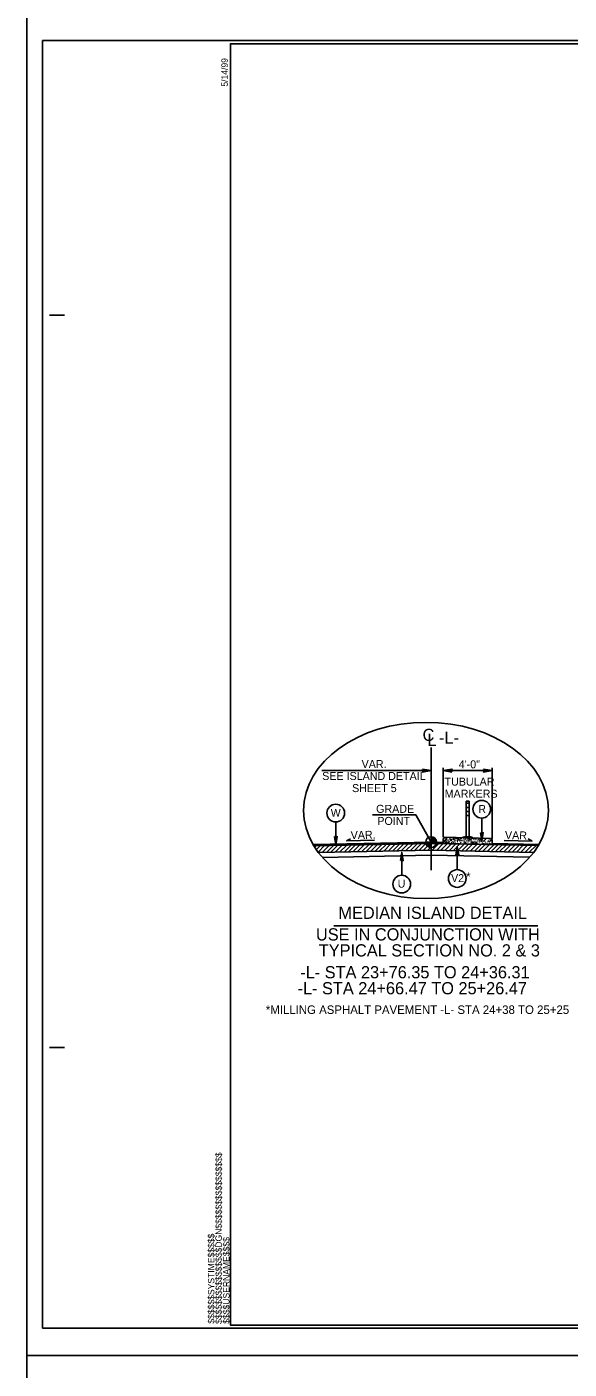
# Model space of a CAD drawing. Extents: x 1901718 to 1902220, y 193828 to 194187.
# Drawn here: x 1901965.8 to 1902010.3, y 193936.9 to 194046.9 of the extents above; entities that cross this region are included whole.
import ezdxf

# ---------------------------------------------------------------- set-up
doc = ezdxf.new("R2010")
doc.units = 0
for name, color, linetype in [('Old_Level_1', 7, 'Continuous'), ('Old_Level_11', 7, 'Continuous'), ('Old_Level_19', 7, 'Continuous'), ('Old_Level_2', 7, 'Continuous'), ('Old_Level_20', 7, 'Continuous'), ('Old_Level_3', 7, 'Continuous'), ('Prop Dimension', 7, 'Continuous'), ('Prop Dimension Text', 7, 'Continuous'), ('Sheet Border Standard 30in CELL', 7, 'Continuous'), ('Sheet Cutting Line CELL', 7, 'Continuous'), ('Sheet Plot Border Inside CELL', 7, 'Continuous'), ('Sheet Plot Border Outside CELL', 7, 'Continuous'), ('Typical Curb CELL', 7, 'Continuous'), ('Typical Terminator CELL', 7, 'Continuous')]:
    doc.layers.add(name, color=color, linetype=linetype)

# ---------------------------------------------------------------- blocks, each defined once
blk = doc.blocks.new('TERMINATOR')
at = {"layer": 'Typical Terminator CELL'}
blk.add_lwpolyline([(-0.469, 0.081), (0, 0), (-0.471, -0.083), (-0.411, 0)], close=True, dxfattribs=at)

msp = doc.modelspace()

# ---------------------------------------------------------------- linework, layer by layer
at = {"layer": 'Old_Level_1'}
for p, q in [((1901998.99, 193977.77), (1901998.99, 193987.83)), ((1901999.99, 193980.5), (1901999.99, 193986.17)), ((1902001.87, 193980.52), (1902001.87, 193983.43)), ((1902001.87, 193983.43), (1902002.12, 193983.43)), ((1902001.87, 193983.26), (1902002.12, 193983.26)), ((1902001.87, 193982.93), (1902002.12, 193982.93)), ((1902002.12, 193980.51), (1902002.12, 193983.43)), ((1902001.87, 193982.59), (1902002.12, 193982.59)), ((1902001.87, 193982.26), (1902002.12, 193982.26)), ((1901998.99, 193980.08), (1901989.32, 193979.89)), ((1901998.99, 193979.98), (1901989.38, 193979.78)), ((1901989.44, 193979.69), (1901989.54, 193979.79)), ((1901989.58, 193979.47), (1901989.9, 193979.79)), ((1901989.73, 193979.27), (1901990.26, 193979.8)), ((1901990.05, 193979.23), (1901990.62, 193979.81)), ((1901990.41, 193979.24), (1901990.98, 193979.81)), ((1901990.77, 193979.25), (1901991.34, 193979.82)), ((1901991.13, 193979.26), (1901991.7, 193979.83)), ((1901991.49, 193979.26), (1901992.07, 193979.84)), ((1901991.85, 193979.27), (1901992.43, 193979.84)), ((1901992.05, 193980.2), (1901992.38, 193980.36)), ((1901994.35, 193980.24), (1901992.05, 193980.2)), ((1901992.21, 193979.28), (1901992.79, 193979.85)), ((1901992.57, 193979.28), (1901993.15, 193979.86)), ((1901992.93, 193979.29), (1901993.51, 193979.87)), ((1901993.3, 193979.3), (1901993.87, 193979.87)), ((1901993.66, 193979.31), (1901994.23, 193979.88)), ((1901994.02, 193979.31), (1901994.59, 193979.89)), ((1901994.38, 193979.32), (1901994.95, 193979.89)), ((1901994.74, 193979.33), (1901995.31, 193979.9)), ((1901995.1, 193979.34), (1901995.67, 193979.91)), ((1901995.46, 193979.34), (1901996.03, 193979.92)), ((1901995.82, 193979.35), (1901996.39, 193979.92)), ((1901995.82, 193979.35), (1901996.01, 193979.54)), ((1901996.18, 193979.36), (1901996.76, 193979.93)), ((1901996.54, 193979.36), (1901997.12, 193979.94)), ((1901996.9, 193979.37), (1901997.48, 193979.94)), ((1901997.26, 193979.38), (1901997.84, 193979.95)), ((1901997.62, 193979.39), (1901998.2, 193979.96)), ((1901997.99, 193979.39), (1901998.56, 193979.97)), ((1901998.35, 193979.4), (1901998.7, 193979.75)), ((1901998.55, 193980.08), (1901998.99, 193980.08)), ((1901998.71, 193979.41), (1901998.94, 193979.64)), ((1901998.99, 193980.08), (1901998.99, 193980.52)), ((1901998.99, 193980.08), (1901999.99, 193980.06)), ((1901999.43, 193980.08), (1901998.99, 193980.08)), ((1901998.99, 193979.64), (1901998.99, 193980.08)), ((1901998.99, 193980.08), (1901998.99, 193979.64)), ((1901998.99, 193979.98), (1902007.77, 193979.8)), ((1901999.07, 193979.41), (1901999.62, 193979.96)), ((1901999.42, 193979.4), (1901999.97, 193979.96)), ((1901999.76, 193979.4), (1902000.31, 193979.95)), ((1902000.11, 193979.39), (1902000.66, 193979.94)), ((1902000.46, 193979.38), (1902001.01, 193979.93)), ((1902000.8, 193979.38), (1902001.35, 193979.93)), ((1902001.15, 193979.37), (1902001.7, 193979.92)), ((1902001.5, 193979.36), (1902002.05, 193979.91)), ((1902001.84, 193979.36), (1902002.39, 193979.91)), ((1902002.19, 193979.35), (1902002.74, 193979.9)), ((1902002.54, 193979.34), (1902003.09, 193979.89)), ((1902002.88, 193979.34), (1902003.43, 193979.89)), ((1902003.23, 193979.33), (1902003.78, 193979.88)), ((1902003.58, 193979.32), (1902004.13, 193979.87)), ((1902003.92, 193979.31), (1902004.47, 193979.87)), ((1902003.99, 193979.98), (1902007.84, 193979.9)), ((1902004.27, 193979.31), (1902004.82, 193979.86)), ((1902004.61, 193979.3), (1902005.17, 193979.85)), ((1902004.96, 193979.29), (1902005.51, 193979.84)), ((1902004.97, 193980.22), (1902007.27, 193980.17)), ((1902005.31, 193979.29), (1902005.86, 193979.84)), ((1902005.65, 193979.28), (1902006.21, 193979.83)), ((1902006, 193979.27), (1902006.55, 193979.82)), ((1902006.35, 193979.27), (1902006.9, 193979.82)), ((1902006.69, 193979.26), (1902007.25, 193979.81)), ((1902007.27, 193980.17), (1902006.95, 193980.36)), ((1902007.04, 193979.25), (1902007.59, 193979.8)), ((1901998.99, 193979.41), (1901989.76, 193979.23)), ((1901998.99, 193979), (1901990.09, 193978.82)), ((1901998.99, 193979.41), (1902007.4, 193979.24)), ((1901998.99, 193979), (1902007.07, 193978.84)), ((1902000.8, 193979.38), (1902000.85, 193979.42)), ((1902007.39, 193979.25), (1902007.45, 193979.3))]:
    msp.add_line(p, q, dxfattribs=at)
for points in [[(1902001.87, 193983.26), (1902002.12, 193983.26), (1902002.12, 193982.93), (1902001.87, 193982.93)], [(1902001.87, 193982.59), (1902002.12, 193982.59), (1902002.12, 193982.26), (1902001.87, 193982.26)]]:
    msp.add_lwpolyline(points, close=True, dxfattribs=at)
for points in [[(1901998.55, 193980.08), (1901998.55, 193980.03)], [(1901998.56, 193980.08), (1901998.56, 193979.98)], [(1901998.57, 193980.08), (1901998.57, 193979.95)], [(1901998.58, 193980.08), (1901998.58, 193979.92)], [(1901998.59, 193980.08), (1901998.59, 193979.9)], [(1901998.6, 193980.08), (1901998.6, 193979.88)], [(1901998.6, 193980.08), (1901998.6, 193979.87)], [(1901998.61, 193980.08), (1901998.61, 193979.85)], [(1901998.62, 193980.08), (1901998.62, 193979.84)], [(1901998.63, 193980.08), (1901998.63, 193979.82)], [(1901998.64, 193980.08), (1901998.64, 193979.81)], [(1901998.65, 193980.08), (1901998.65, 193979.8)], [(1901998.66, 193980.08), (1901998.66, 193979.79)], [(1901998.67, 193980.08), (1901998.67, 193979.78)], [(1901998.68, 193980.08), (1901998.68, 193979.77)], [(1901998.68, 193980.08), (1901998.68, 193979.76)], [(1901998.69, 193980.08), (1901998.69, 193979.75)], [(1901998.7, 193980.08), (1901998.7, 193979.75)], [(1901998.71, 193980.08), (1901998.71, 193979.74)], [(1901998.72, 193980.08), (1901998.72, 193979.73)], [(1901998.73, 193980.08), (1901998.73, 193979.72)], [(1901998.74, 193980.08), (1901998.74, 193979.72)], [(1901998.75, 193980.08), (1901998.75, 193979.71)], [(1901998.75, 193980.08), (1901998.75, 193979.71)], [(1901998.76, 193980.08), (1901998.76, 193979.7)], [(1901998.77, 193980.08), (1901998.77, 193979.7)], [(1901998.78, 193980.08), (1901998.78, 193979.69)], [(1901998.79, 193980.08), (1901998.79, 193979.69)], [(1901998.8, 193980.08), (1901998.8, 193979.68)], [(1901998.81, 193980.08), (1901998.81, 193979.68)], [(1901998.82, 193980.08), (1901998.82, 193979.67)], [(1901998.82, 193980.08), (1901998.82, 193979.67)], [(1901998.83, 193980.08), (1901998.83, 193979.67)], [(1901998.84, 193980.08), (1901998.84, 193979.66)], [(1901998.85, 193980.08), (1901998.85, 193979.66)], [(1901998.86, 193980.08), (1901998.86, 193979.66)], [(1901998.87, 193980.08), (1901998.87, 193979.66)], [(1901998.88, 193980.08), (1901998.88, 193979.65)], [(1901998.89, 193980.08), (1901998.89, 193979.65)], [(1901998.9, 193980.08), (1901998.9, 193979.65)], [(1901998.9, 193980.08), (1901998.9, 193979.65)], [(1901998.91, 193980.08), (1901998.91, 193979.64)], [(1901998.92, 193980.08), (1901998.92, 193979.64)], [(1901998.93, 193980.08), (1901998.93, 193979.64)], [(1901998.94, 193980.08), (1901998.94, 193979.64)], [(1901998.95, 193980.08), (1901998.95, 193979.64)], [(1901998.96, 193980.08), (1901998.96, 193979.64)], [(1901998.97, 193980.08), (1901998.97, 193979.64)], [(1901998.97, 193980.08), (1901998.97, 193979.64)], [(1901998.98, 193980.08), (1901998.98, 193979.64), (1901998.98, 193979.64)], [(1901998.99, 193980.52), (1901998.99, 193980.52), (1901998.99, 193980.08)], [(1901999, 193980.52), (1901999, 193980.08)], [(1901999.01, 193980.52), (1901999.01, 193980.08)], [(1901999.02, 193980.52), (1901999.02, 193980.08)], [(1901999.03, 193980.52), (1901999.03, 193980.08)], [(1901999.04, 193980.52), (1901999.04, 193980.08)], [(1901999.05, 193980.52), (1901999.05, 193980.08)], [(1901999.06, 193980.52), (1901999.06, 193980.08)], [(1901999.07, 193980.51), (1901999.07, 193980.08)], [(1901999.07, 193980.51), (1901999.07, 193980.08)], [(1901999.08, 193980.51), (1901999.08, 193980.08)], [(1901999.09, 193980.51), (1901999.09, 193980.08)], [(1901999.1, 193980.51), (1901999.1, 193980.08)], [(1901999.11, 193980.5), (1901999.11, 193980.08)], [(1901999.12, 193980.5), (1901999.12, 193980.08)], [(1901999.13, 193980.5), (1901999.13, 193980.08)], [(1901999.14, 193980.5), (1901999.14, 193980.08)], [(1901999.14, 193980.49), (1901999.14, 193980.08)], [(1901999.15, 193980.49), (1901999.15, 193980.08)], [(1901999.16, 193980.48), (1901999.16, 193980.08)], [(1901999.17, 193980.48), (1901999.17, 193980.08)], [(1901999.18, 193980.48), (1901999.18, 193980.08)], [(1901999.19, 193980.47), (1901999.19, 193980.08)], [(1901999.2, 193980.47), (1901999.2, 193980.08)], [(1901999.21, 193980.46), (1901999.21, 193980.08)], [(1901999.22, 193980.46), (1901999.22, 193980.08)], [(1901999.22, 193980.45), (1901999.22, 193980.08)], [(1901999.23, 193980.45), (1901999.23, 193980.08)], [(1901999.24, 193980.44), (1901999.24, 193980.08)], [(1901999.25, 193980.43), (1901999.25, 193980.08)], [(1901999.26, 193980.43), (1901999.26, 193980.08)], [(1901999.27, 193980.42), (1901999.27, 193980.08)], [(1901999.28, 193980.41), (1901999.28, 193980.08)], [(1901999.29, 193980.41), (1901999.29, 193980.08)], [(1901999.29, 193980.4), (1901999.29, 193980.08)], [(1901999.3, 193980.39), (1901999.3, 193980.08)], [(1901999.31, 193980.38), (1901999.31, 193980.08)], [(1901999.32, 193980.37), (1901999.32, 193980.08)], [(1901999.33, 193980.36), (1901999.33, 193980.08)], [(1901999.34, 193980.35), (1901999.34, 193980.08)], [(1901999.35, 193980.34), (1901999.35, 193980.08)], [(1901999.36, 193980.33), (1901999.36, 193980.08)], [(1901999.36, 193980.31), (1901999.36, 193980.08)], [(1901999.37, 193980.3), (1901999.37, 193980.08)], [(1901999.38, 193980.28), (1901999.38, 193980.08)], [(1901999.39, 193980.26), (1901999.39, 193980.08)], [(1901999.4, 193980.24), (1901999.4, 193980.08)], [(1901999.41, 193980.22), (1901999.41, 193980.08)], [(1901999.42, 193980.19), (1901999.42, 193980.08)], [(1901999.43, 193980.14), (1901999.43, 193980.08)]]:
    msp.add_lwpolyline(points, dxfattribs=at)
msp.add_circle((1901998.99, 193980.08), 0.441, dxfattribs=at)
for start, end in [(179.9905, 269.9905), (359.9905, 89.9905)]:
    msp.add_arc((1901998.99, 193980.08), 0.441, start, end, dxfattribs=at)
msp.add_ellipse((1902001.99, 193980.43), major_axis=(0.448, -0.012), ratio=0.205578, start_param=6.283185, end_param=9.424778, dxfattribs=at)
at = {"layer": 'Old_Level_11'}
for p, q in [((1901991.17, 193981.74), (1901991.17, 193979.86)), ((1902003.14, 193982.05), (1902003.14, 193980.18)), ((1902001.13, 193977.83), (1902001.13, 193979.7)), ((1901996.58, 193977.36), (1901996.58, 193979.24)), ((1901991.02, 193973.22), (1902007.74, 193973.22))]:
    msp.add_line(p, q, dxfattribs=at)
for points in [[(1902003.03, 193980.85), (1902003.14, 193980.18), (1902003.26, 193980.85), (1902003.14, 193980.77)], [(1901991.06, 193980.53), (1901991.17, 193979.86), (1901991.29, 193980.54), (1901991.17, 193980.45)], [(1902001.01, 193979.03), (1902001.13, 193979.7), (1902001.25, 193979.03), (1902001.13, 193979.11)], [(1901996.47, 193978.57), (1901996.58, 193979.24), (1901996.7, 193978.56), (1901996.58, 193978.65)]]:
    msp.add_lwpolyline(points, close=True, dxfattribs=at)
for centre in [(1901991.17, 193982.46), (1902003.14, 193982.78), (1901996.58, 193976.64), (1902001.13, 193977.1)]:
    msp.add_circle(centre, 0.725, dxfattribs=at)
at = {"layer": 'Old_Level_3'}
for q in [(1901994.19, 193982.32), (1901998.99, 193980.08)]:
    msp.add_line((1901997.75, 193982.32), q, dxfattribs=at)
at = {"layer": 'Prop Dimension'}
for p, q in [((1902003.99, 193980.37), (1902003.99, 193986.17)), ((1901990.02, 193985.94), (1901998.99, 193985.94)), ((1901999.99, 193985.94), (1902003.99, 193985.94))]:
    msp.add_line(p, q, dxfattribs=at)
at = {"layer": 'Sheet Border Standard 30in CELL'}
for p, q in [((1901982.64, 194045.51), (1901982.64, 194045.51)), ((1901967.69, 194023.26), (1901968.94, 194023.26)), ((1901967.69, 193963.26), (1901968.94, 193963.26))]:
    msp.add_line(p, q, dxfattribs=at)
msp.add_lwpolyline([(1902132.54, 194045.51), (1901982.54, 194045.51), (1901982.54, 193940.51), (1902132.54, 193940.51)], close=True, dxfattribs=at)
at = {"layer": 'Sheet Cutting Line CELL'}
for p, q in [((1901965.84, 194048.01), (1901965.84, 193938.01)), ((1901965.84, 193938.01), (1902134.24, 193938.01)), ((1902134.24, 193938.01), (1901965.84, 193938.01)), ((1901965.84, 193938.01), (1901965.84, 193828.01))]:
    msp.add_line(p, q, dxfattribs=at)
at = {"layer": 'Sheet Plot Border Inside CELL'}
msp.add_lwpolyline([(1902133.79, 194045.77), (1901967.14, 194045.77), (1901967.14, 193940.26), (1902133.79, 193940.26)], close=True, dxfattribs=at)
at = {"layer": 'Sheet Plot Border Outside CELL'}
for points in [[(1902134.24, 194048.01), (1901965.84, 194048.01), (1901965.84, 193938.01), (1902134.24, 193938.01)], [(1902134.24, 193938.01), (1901965.84, 193938.01), (1901965.84, 193828.01), (1902134.24, 193828.01)]]:
    msp.add_lwpolyline(points, close=True, dxfattribs=at)
at = {"layer": 'Typical Curb CELL'}
for p, q in [((1901999.99, 193979.96), (1901999.99, 193980.35)), ((1901999.99, 193980.14), (1901999.99, 193980.14)), ((1901999.99, 193979.96), (1902003.99, 193979.88)), ((1902000.12, 193980.48), (1902003.87, 193980.38)), ((1902000.25, 193980.11), (1902000.17, 193980.1)), ((1902000.17, 193980.1), (1902000.21, 193979.99)), ((1902000.21, 193980.35), (1902000.3, 193980.35)), ((1902000.22, 193980.27), (1902000.21, 193980.35)), ((1902000.21, 193979.99), (1902000.25, 193980.11)), ((1902000.3, 193980.35), (1902000.22, 193980.27)), ((1902000.59, 193980.29), (1902000.68, 193980.29)), ((1902000.6, 193980.2), (1902000.59, 193980.29)), ((1902000.68, 193980.29), (1902000.6, 193980.2)), ((1902000.88, 193980.35), (1902000.77, 193980.39)), ((1902000.77, 193980.39), (1902000.85, 193980.28)), ((1902000.85, 193980.28), (1902000.88, 193980.35)), ((1902001.22, 193980.42), (1902001.26, 193980.27)), ((1902001.3, 193980.36), (1902001.22, 193980.42)), ((1902001.26, 193980.27), (1902001.3, 193980.36)), ((1902001.83, 193980.07), (1902001.75, 193980.06)), ((1902001.75, 193980.06), (1902001.79, 193979.95)), ((1902001.79, 193979.95), (1902001.83, 193980.07)), ((1902002.08, 193980.39), (1902002.13, 193980.24)), ((1902002.17, 193980.33), (1902002.08, 193980.39)), ((1902002.13, 193980.24), (1902002.17, 193980.33)), ((1902002.39, 193980.1), (1902002.48, 193980.05)), ((1902002.42, 193979.97), (1902002.39, 193980.1)), ((1902002.48, 193980.05), (1902002.42, 193979.97)), ((1902002.75, 193980.06), (1902002.67, 193980.04)), ((1902002.67, 193980.04), (1902002.71, 193979.93)), ((1902002.71, 193979.93), (1902002.75, 193980.06)), ((1902003, 193980.37), (1902003.04, 193980.22)), ((1902003.09, 193980.31), (1902003, 193980.37)), ((1902003.04, 193980.22), (1902003.09, 193980.31)), ((1902003.39, 193980.22), (1902003.3, 193980.22)), ((1902003.3, 193980.22), (1902003.38, 193980.14)), ((1902003.38, 193980.14), (1902003.39, 193980.22)), ((1902003.85, 193980.27), (1902003.94, 193980.27)), ((1902003.86, 193980.19), (1902003.85, 193980.27)), ((1902003.94, 193980.27), (1902003.86, 193980.19)), ((1902003.99, 193979.88), (1902003.99, 193980.25)), ((1902003.99, 193980.07), (1902003.99, 193980.08))]:
    msp.add_line(p, q, dxfattribs=at)
for centre in [(1901998.66, 193979.97), (1901998.92, 193979.95), (1902000.01, 193979.98), (1902000.01, 193979.96), (1902000.06, 193980.3), (1902000.09, 193980.1), (1902000.1, 193980.18), (1902000.15, 193980.44), (1902000.15, 193980.01), (1902000.18, 193980.21), (1902000.2, 193980.04), (1902000.28, 193980.01), (1902000.3, 193980.22), (1902000.31, 193980.18), (1902000.39, 193980.04), (1902000.42, 193979.97), (1902000.44, 193980.24), (1902000.45, 193980.14), (1902000.5, 193980.09), (1902000.53, 193980.37), (1902000.67, 193980.05), (1902000.76, 193980.1), (1902000.84, 193980.06), (1902000.91, 193980.17), (1902000.96, 193980.37), (1902001, 193980), (1902001.02, 193980.21), (1902001.11, 193980.36), (1902001.14, 193979.96), (1902001.15, 193980.23), (1902001.17, 193980.13), (1902001.3, 193980.2), (1902001.4, 193980.34), (1902001.4, 193979.94), (1902001.42, 193980.06), (1902001.45, 193980.2), (1902001.49, 193980.38), (1902001.59, 193980.21), (1902001.68, 193980.35), (1902001.69, 193979.95), (1902001.7, 193980.08), (1902001.73, 193980.21), (1902001.82, 193980.34), (1902001.86, 193979.97), (1902001.88, 193980.19), (1902001.97, 193980.33), (1902002, 193979.93), (1902002.02, 193980.2), (1902002.03, 193980.1), (1902002.17, 193980.17), (1902002.26, 193980.31), (1902002.27, 193979.94), (1902002.28, 193980.04), (1902002.31, 193980.17), (1902002.35, 193980.36), (1902002.47, 193980.38), (1902002.5, 193980.29), (1902002.51, 193979.94), (1902002.59, 193980.05), (1902002.59, 193979.92), (1902002.61, 193980.36), (1902002.6, 193980.13), (1902002.62, 193980.33), (1902002.74, 193980.33), (1902002.78, 193979.96), (1902002.8, 193980.17), (1902002.89, 193980.31), (1902002.92, 193979.92), (1902002.94, 193980.18), (1902002.95, 193980.09), (1902003.09, 193980.15), (1902003.18, 193980.3), (1902003.18, 193979.93), (1902003.2, 193980.02), (1902003.23, 193980.16), (1902003.32, 193979.98), (1902003.45, 193980.31), (1902003.48, 193980.02), (1902003.6, 193979.97), (1902003.67, 193980.12), (1902003.69, 193980.22), (1902003.79, 193980.36), (1902003.79, 193979.98), (1902003.8, 193980.14), (1902003.97, 193979.92)]:
    msp.add_circle(centre, 0.00635, dxfattribs=at)
for centre, start, end in [((1902000.12, 193980.35), 88.5107, 180), ((1902003.87, 193980.25), 0, 88.5107)]:
    msp.add_arc(centre, 0.125, start, end, dxfattribs=at)
msp.add_ellipse((1901998.57, 193982.68), major_axis=(10.04, 0), ratio=0.718852, dxfattribs=at)

# ---------------------------------------------------------------- block references
at = {"layer": 'Prop Dimension', "xscale": 1.5, "yscale": 1.5}
for p in [(1901998.99, 193985.94), (1902003.99, 193985.94)]:
    msp.add_blockref('TERMINATOR', p, dxfattribs=at)
at = {"layer": 'Prop Dimension', "xscale": 1.5, "yscale": 1.5, "rotation": 180}
msp.add_blockref('TERMINATOR', (1901999.99, 193985.94), dxfattribs=at)

# ---------------------------------------------------------------- texts
at = {"layer": 'Old_Level_19'}
for s, p in [('MEDIAN ISLAND DETAIL', (1901991.39, 193973.79)), ('USE IN CONJUNCTION WITH ', (1901989.55, 193972.02)), ('TYPICAL SECTION NO. 2 & 3', (1901989.78, 193970.71)), ('-L- STA 23+76.35 TO 24+36.31', (1901988.26, 193968.92)), ('-L- STA 24+66.47 TO 25+26.47', (1901988.04, 193967.61))]:
    msp.add_text(s, height=1, dxfattribs=at).set_placement(p)
at = {"layer": 'Old_Level_2'}
msp.add_text('C', height=1, dxfattribs=at).set_placement((1901998.29, 193988.37))
for s, height, rotation, p in [('L', 1, 359.9469, (1901998.69, 193987.96)), ('-L-', 1, 359.9469, (1901999.64, 193988.14)), ('VAR.', 0.656, 1.1916, (1901992.4, 193980.32)), ('VAR.', 0.656, 358.8084, (1902005.04, 193980.33))]:
    msp.add_text(s, height=height, rotation=rotation, dxfattribs=at).set_placement(p)
at = {"layer": 'Old_Level_20'}
for s, p in [('W', (1901990.76, 193982.16)), ('R', (1902002.86, 193982.47)), ('V2', (1902000.63, 193976.81)), ('U', (1901996.25, 193976.35))]:
    msp.add_text(s, height=0.649, dxfattribs=at).set_placement(p)
at = {"layer": 'Old_Level_3'}
for s, p in [('GRADE', (1901994.48, 193982.48)), ('POINT', (1901994.58, 193981.49))]:
    msp.add_text(s, height=0.656, dxfattribs=at).set_placement(p)
at = {"layer": 'Prop Dimension'}
for s, p in [('VAR.', (1901993.29, 193986.15)), ('4\'-0" ', (1902001.25, 193986.13)), ('SEE ISLAND DETAIL', (1901990.06, 193985.17)), ('TUBULAR', (1902000.09, 193984.71)), ('SHEET 5', (1901992.51, 193984.18)), ('MARKERS', (1902000.1, 193983.72))]:
    msp.add_text(s, height=0.656, dxfattribs=at).set_placement(p)
at = {"layer": 'Prop Dimension Text'}
for s, p in [('*', (1902001.86, 193976.91)), ('*MILLING ASPHALT PAVEMENT -L- STA 24+38 TO 25+25', (1901985.44, 193966))]:
    msp.add_text(s, height=0.7, rotation=360, dxfattribs=at).set_placement(p)
at = {"layer": 'Sheet Border Standard 30in CELL'}
for s, p in [('5/14/99', (1901982.32, 194041.99)), ('$$$$$$$$$$$$$$$$DGN$$$$$$$$$$$$$$$$', (1901981.83, 193940.6)), ('$$$$$$SYSTIME$$$$$', (1901981.22, 193940.62)), ('$$$$USERNAME$$$$', (1901982.46, 193940.61))]:
    msp.add_text(s, height=0.525, rotation=90, dxfattribs=at).set_placement(p)

doc.saveas('drawing.dxf')
